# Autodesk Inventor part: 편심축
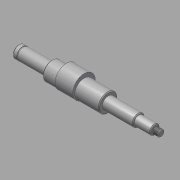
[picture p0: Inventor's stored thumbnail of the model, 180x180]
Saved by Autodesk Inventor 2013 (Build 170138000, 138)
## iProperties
Created: 2015-09
Part Number: 편심축
Material: 강철, 연강
Document SubType Name: Modeling
Designer: mduedu
Density: 1 g/cm^3
Author: mduedu
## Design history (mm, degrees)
sketch "스케치1"
  geometry: L1 (-88.5, 0)-(88.5, 0); L2 (-88.5, 0)-(-88.5, 7.5); L3 (-88.5, 7.5)-(-47.35, 7.5); L4 (-47.35, 7.5)-(-47.35, 11.5); L5 (-47.35, 11.5)-(22.65, 11.5); L6 (22.65, 11.5)-(22.65, 7.5); L7 (22.65, 7.5)-(60.65, 7.5); L8 (60.65, 7.5)-(60.65, 6); L9 (60.65, 6)-(80.65, 6); L10 (80.65, 6)-(80.65, 3); L11 (80.65, 3)-(81.65, 3); L12 (81.65, 3)-(81.65, 4); L13 (81.65, 4)-(88.5, 4); L14 (88.5, 4)-(88.5, 0); 2 further points
  constraints: 28 end point, 10 parallel, 2 perpendicular, 1 coincident, 1 collinear, 1 horizontal, 1 midpoint
  dimensions: "d0" = 41.15 distance of L2.end L3.end; "d2" = 70 distance of L4.end L5.end; "d3" = 38 distance of L6.end L7.end; "d4" = 177 distance of L1.start L1.end; "d5" = 20 distance of L8.end L9.end; "d6" = 1 distance of L10.end L11.end; "d7" = 8 diameter of L13 L1; "d8" = 6 diameter of L11 L1; "d9" = 12 diameter of L9 L1; "d10" = 15 diameter of L7 L1; "d11" = 23 diameter of L5 L1; "d12" = 15 diameter of L3 L1
revolve "회전1" sketch "스케치1" stored, may be unused: angle "d13" = 90 deg
sketch "스케치2"
  geometry: L1 (-88.5, 7.5)-(-47.35, 7.5) reference; L2 (-88.5, -7.5)-(-88.5, 7.5) reference; L3 (88.5, -4)-(88.5, 4) reference; L4 (-88.5, 0)-(88.5, 0); L5 (-83.5, 7.5)-(-82.35, 7.5); L6 (-82.35, 7.5)-(-82.35, 7.15); L7 (-82.35, 7.15)-(-83.5, 7.15); L8 (-83.5, 7.15)-(-83.5, 7.5); 1 further point
  constraints: 10 end point, 2 midpoint, 2 parallel, 1 horizontal, 1 perpendicular, 1 point on line
  dimensions: "d14" = 5 distance between parallel lines of L8 L2; "d15" = 14.3 diameter of L7 L4; "d16" = 1.15 distance of L6.end L7.end
revolve "회전2" sketch "스케치2" stored, may be unused: angle "d17" = 90 deg
node "작업 평면1"
sketch "스케치3"
  geometry: C1 r 11.5 at (0, 0) reference; C2 r 14 at (0, 2.5); 1 further point
  constraints: 1 centre point, 1 tangent, 1 vertical alignment
  dimensions: "d19" = 28 diameter of C2
extrude "돌출1" join sketch "스케치3" distance "d21" = 22; taper "d22" = 0 deg
node "작업 평면2"
sketch "스케치4"
  geometry: L1 (10, 7.5)-(10, -7.5) reference; L2 (-10, 6)-(-10, -6) reference; L3 (10, 0)-(-10, 0); L4 (-5, -2)-(3, -2); L5 (3, 2)-(-5, 2); A1 r 2 centre (3, 0) between (3, -2) and (3, 2); A2 r 2 centre (-5, 0) between (-5, 2) and (-5, -2); 1 further point
  constraints: 6 end point, 4 point on circle, 4 tangent, 2 centre point, 2 midpoint, 2 parallel, 1 point on line
  dimensions: "d23" = 4 distance between parallel lines of L5 L4; "d25" = 12 dimension on A2 A1; "d26" = 3 distance edge to line of A2 L2
extrude "돌출2" cut sketch "스케치4" distance "d27" = 2.5; taper "d28" = 0 deg
chamfer "모따기1" distance "d29" = 1; stored, may be unused: second distance "d30" = 2, angle "d31" = 45 deg
feature "스레드1" dims "d32" = 10, "d33" = 0
chamfer "모따기2" distance "d34" = 1; stored, may be unused: second distance "d35" = 2, angle "d36" = 45 deg
chamfer "모따기3" distance "d37" = 1; stored, may be unused: second distance "d38" = 2, angle "d39" = 45 deg
node "솔리드1"
